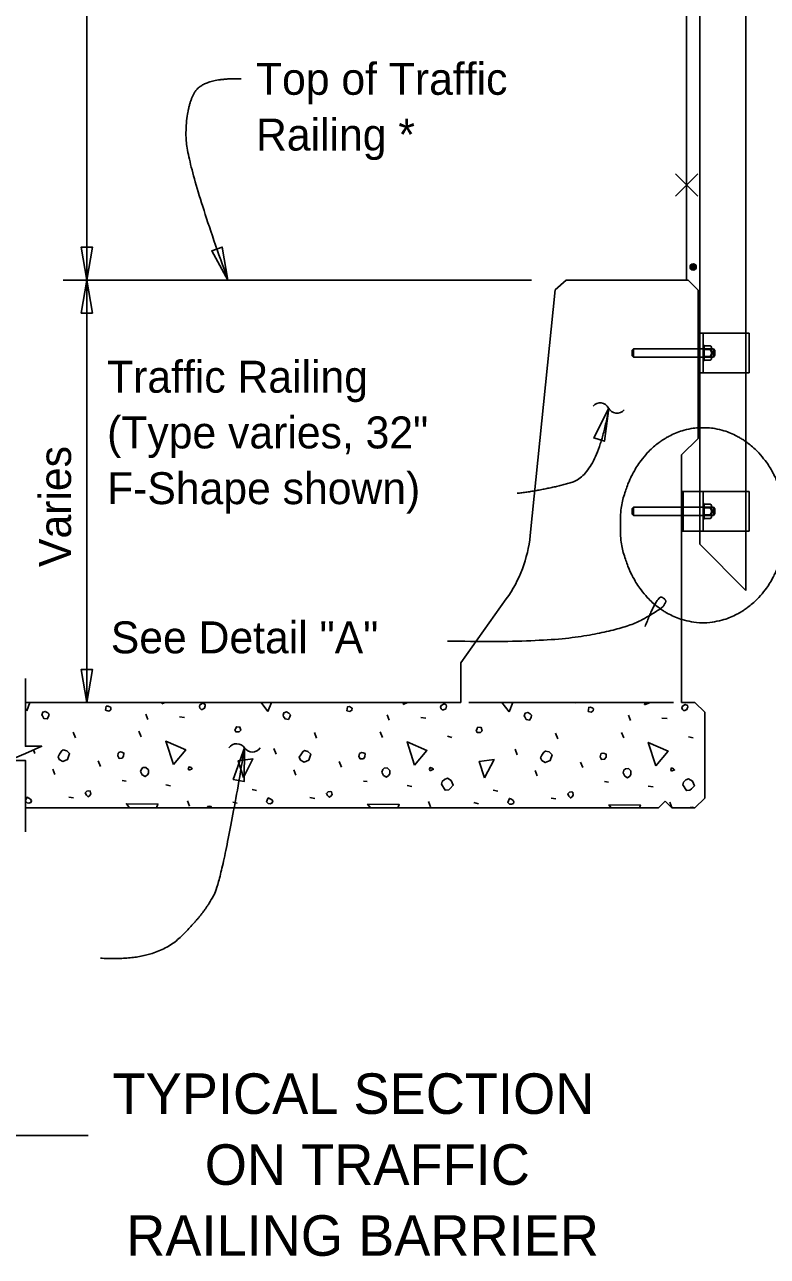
# Model space of a CAD drawing. Extents: x 0 to 41.1, y 0 to 25.9.
# Drawn here: x 29.01 to 33.7, y 11.06 to 18.84 of the extents above; entities that cross this region are included whole.
import ezdxf

# ---------------------------------------------------------------- set-up
doc = ezdxf.new("R2010")
doc.units = 0
for name, color, linetype in [('Dimension', 7, 'Continuous'), ('Miscellaneous', 7, 'Continuous'), ('SteelMisc', 7, 'Continuous'), ('SteelMisc_h', 7, 'Continuous'), ('SupstrConc', 7, 'Continuous'), ('SupstrConc_h', 7, 'Continuous'), ('TextStructures', 7, 'Continuous')]:
    doc.layers.add(name, color=color, linetype=linetype)

msp = doc.modelspace()

# ---------------------------------------------------------------- linework, layer by layer
at = {"layer": 'Dimension'}
for p, q in [((29.4061, 14.5579), (29.4061, 23.2246)), ((32.214, 17.2246), (29.2561, 17.2246)), ((23.6151, 11.8234), (29.4153, 11.8234))]:
    msp.add_line(p, q, dxfattribs=at)
for points in [[(29.4061, 17.2246), (29.3708, 17.4328), (29.4413, 17.4328)], [(30.2977, 17.2246), (30.2616, 17.4327), (30.1951, 17.4092)], [(29.4061, 17.2246), (29.3708, 17.0163), (29.4413, 17.0163)], [(32.7026, 16.4167), (32.6085, 16.2276), (32.676, 16.2071)], [(29.4061, 14.5579), (29.4413, 14.7662), (29.3708, 14.7662)], [(30.403, 14.2704), (30.3312, 14.0717), (30.4006, 14.0591)]]:
    msp.add_lwpolyline(points, close=True, dxfattribs=at)
msp.add_lwpolyline([(29.0176, 14.7079), (29.0176, 14.2808), (29.1209, 14.2808), (29.0176, 14.2358), (28.9142, 14.1908), (29.0176, 14.1908), (29.0176, 13.7412)], dxfattribs=at)
for centre, start, end in [((32.6489, 16.3894), 27.32823, 139.05545), ((32.7548, 16.4441), 207.32823, 319.05545), ((30.3527, 14.2371), 33.91896, 145.64618), ((30.4517, 14.3036), 213.91896, 325.64618)]:
    msp.add_arc(centre, 0.0596, start, end, dxfattribs=at)
for points, degree in [([(30.3802, 18.496), (30.1383, 18.5019), (30.0322, 18.3129), (30.0322, 17.9586), (30.2976, 17.2245)], 2), ([(32.1233, 15.878), (32.2959, 15.8977), (32.6322, 15.993), (32.7026, 16.4166)], 2), ([(33.2986, 15.0608), (33.3336, 15.0608), (33.3683, 15.0649), (33.4362, 15.0811), (33.4694, 15.0931), (33.5172, 15.1167), (33.5328, 15.1255), (33.5556, 15.14), (33.5631, 15.1451), (33.5779, 15.1557), (33.5851, 15.1612), (33.6208, 15.1896), (33.6471, 15.2155), (33.695, 15.2726), (33.7165, 15.3038), (33.7399, 15.3457), (33.7444, 15.3542), (33.7531, 15.3715), (33.7573, 15.3803), (33.7692, 15.4069), (33.7764, 15.4251), (33.8084, 15.5175), (33.8217, 15.5966), (33.8217, 15.7569), (33.8084, 15.836), (33.7764, 15.9283), (33.7692, 15.9465), (33.7573, 15.9731), (33.7531, 15.9819), (33.7444, 15.9992), (33.7399, 16.0077), (33.7165, 16.0496), (33.695, 16.0808), (33.6471, 16.138), (33.6208, 16.1638), (33.5851, 16.1923), (33.5779, 16.1978), (33.5631, 16.2083), (33.5556, 16.2134), (33.5328, 16.2279), (33.5172, 16.2367), (33.4694, 16.2603), (33.4362, 16.2724), (33.3683, 16.2885), (33.3336, 16.2926), (33.2636, 16.2926), (33.2289, 16.2885), (33.1609, 16.2724), (33.1278, 16.2603), (33.08, 16.2367), (33.0644, 16.2279), (33.0416, 16.2134), (33.0341, 16.2083), (33.0193, 16.1978), (33.0121, 16.1923), (32.9764, 16.1638), (32.9501, 16.138), (32.9022, 16.0808), (32.8807, 16.0496), (32.8573, 16.0077), (32.8527, 15.9992), (32.8441, 15.9819), (32.8399, 15.9731), (32.828, 15.9465), (32.8208, 15.9283), (32.7887, 15.836), (32.7755, 15.7569), (32.7755, 15.5966), (32.7887, 15.5175), (32.8208, 15.4251), (32.828, 15.4069), (32.8399, 15.3803), (32.8441, 15.3715), (32.8527, 15.3542), (32.8573, 15.3457), (32.8807, 15.3038), (32.9022, 15.2726), (32.9501, 15.2155), (32.9764, 15.1896), (33.0121, 15.1612), (33.0193, 15.1557), (33.0341, 15.1451), (33.0416, 15.14), (33.0644, 15.1255), (33.08, 15.1167), (33.1278, 15.0931), (33.1609, 15.0811), (33.2289, 15.0649), (33.2636, 15.0608), (33.2986, 15.0608)], 3), ([(31.6835, 14.9449), (32.2811, 14.9325), (32.8178, 15.0224), (33.0428, 15.1547), (33.0535, 15.1766), (33.0697, 15.2026), (33.0105, 15.2403), (32.9324, 15.0361)], 2), ([(29.4916, 12.9427), (29.8372, 12.9194), (30.1609, 13.2347), (30.2688, 13.477), (30.4029, 14.2707)], 2)]:
    msp.add_open_spline(points, degree=degree, dxfattribs=at)
at = {"layer": 'Miscellaneous'}
for p, q in [((33.2653, 17.8952), (33.1239, 17.7539)), ((33.1239, 17.8952), (33.2653, 17.7539)), ((33.2676, 16.8894), (33.278, 16.8894)), ((33.2712, 16.8894), (33.2712, 16.6394)), ((33.2745, 16.8894), (33.2745, 16.6394)), ((33.3586, 16.7756), (33.3586, 16.7548)), ((33.3683, 16.7756), (33.3683, 16.7548)), ((33.278, 16.6394), (33.2676, 16.6394)), ((33.1634, 15.8894), (33.1738, 15.8894)), ((33.167, 15.8894), (33.167, 15.6394)), ((33.1703, 15.8894), (33.1703, 15.6394)), ((33.3586, 15.7756), (33.3586, 15.7548)), ((33.3683, 15.7756), (33.3683, 15.7548)), ((33.1738, 15.6394), (33.1634, 15.6394)), ((30.9661, 14.5579), (30.9674, 14.5576)), ((32.4722, 14.5579), (32.4912, 14.5541)), ((29.7919, 14.4498), (29.7795, 14.4834)), ((31.3157, 14.4462), (31.3033, 14.4798)), ((32.8395, 14.4427), (32.8271, 14.4763)), ((29.9916, 14.4657), (30.0234, 14.4622)), ((31.5154, 14.4622), (31.5473, 14.4586)), ((33.0392, 14.4586), (33.0711, 14.4551)), ((29.334, 14.3349), (29.3199, 14.3702)), ((29.7494, 14.3402), (29.7353, 14.3755)), ((30.8578, 14.3313), (30.8437, 14.3667)), ((31.2732, 14.3366), (31.2591, 14.372)), ((31.6834, 14.3437), (31.7117, 14.3366)), ((32.3816, 14.3278), (32.3675, 14.3632)), ((32.7971, 14.3331), (32.7829, 14.3685)), ((33.2072, 14.3402), (33.2355, 14.3331)), ((29.0777, 14.2341), (29.0682, 14.2578)), ((30.6015, 14.2306), (30.5874, 14.2659)), ((32.1253, 14.227), (32.1112, 14.2624)), ((29.4913, 14.1528), (29.4772, 14.1882)), ((31.0152, 14.1493), (31.001, 14.1846)), ((32.539, 14.1457), (32.5248, 14.1811)), ((29.2032, 14.1015), (29.1908, 14.1351)), ((30.727, 14.098), (30.7146, 14.1316)), ((32.2508, 14.0945), (32.2384, 14.1281)), ((29.6292, 14.0644), (29.654, 14.0609)), ((29.905, 14.0361), (29.935, 14.0308)), ((30.4495, 14.0078), (30.4778, 14.0008)), ((31.153, 14.0609), (31.1778, 14.0573)), ((31.4288, 14.0326), (31.4589, 14.0273)), ((31.9733, 14.0043), (32.0016, 13.9972)), ((32.6769, 14.0573), (32.7016, 14.0538)), ((32.9526, 14.0291), (32.9827, 14.0238)), ((29.2916, 13.9601), (29.3216, 13.9548)), ((30.0535, 13.9018), (30.0411, 13.9354)), ((30.3275, 13.9283), (30.3558, 13.9212)), ((30.8154, 13.9566), (30.8454, 13.9513)), ((31.5773, 13.8982), (31.5649, 13.9318)), ((31.8513, 13.9248), (31.8796, 13.9177)), ((32.3392, 13.953), (32.3693, 13.9477)), ((33.1011, 13.8947), (33.0887, 13.9283))]:
    msp.add_line(p, q, dxfattribs=at)
for points in [[(33.1947, 23.2246), (33.1947, 17.2246)], [(29.0463, 14.5579), (29.0264, 14.5046)], [(29.8802, 14.5488), (29.8831, 14.5579)], [(29.9005, 14.5579), (29.8802, 14.5488)], [(30.1277, 14.5134), (30.1348, 14.5134), (30.1489, 14.5205), (30.1543, 14.5364), (30.1525, 14.5452), (30.1383, 14.5523), (30.1207, 14.5417), (30.1171, 14.5311), (30.1207, 14.5205), (30.1277, 14.5134)], [(30.5502, 14.501), (30.507, 14.5579)], [(30.5715, 14.5579), (30.5502, 14.501)], [(31.4041, 14.5452), (31.408, 14.5579)], [(31.4322, 14.5579), (31.4041, 14.5452)], [(31.6516, 14.5099), (31.6586, 14.5099), (31.6728, 14.517), (31.6781, 14.5329), (31.6763, 14.5417), (31.6622, 14.5488), (31.6445, 14.5382), (31.6409, 14.5276), (31.6445, 14.517), (31.6516, 14.5099)], [(32.074, 14.4975), (32.0282, 14.5579)], [(32.0966, 14.5579), (32.074, 14.4975)], [(32.9279, 14.5417), (32.9329, 14.5579)], [(32.9639, 14.5579), (32.9279, 14.5417)], [(29.0264, 14.5046), (29.0176, 14.5162)], [(29.1254, 14.4728), (29.1343, 14.4569), (29.1555, 14.4533), (29.1643, 14.4692), (29.1678, 14.4834), (29.159, 14.4922), (29.1431, 14.501), (29.1272, 14.4957), (29.1219, 14.4798), (29.1254, 14.4728)], [(29.5249, 14.5081), (29.5444, 14.5028), (29.5567, 14.5117), (29.5585, 14.524), (29.555, 14.5276), (29.5408, 14.5346), (29.5285, 14.5329), (29.5267, 14.5205), (29.5249, 14.5081)], [(30.6492, 14.4692), (30.6581, 14.4533), (30.6793, 14.4498), (30.6881, 14.4657), (30.6917, 14.4798), (30.6828, 14.4887), (30.6669, 14.4975), (30.651, 14.4922), (30.6457, 14.4763), (30.6492, 14.4692)], [(31.0487, 14.5046), (31.0682, 14.4993), (31.0806, 14.5081), (31.0823, 14.5205), (31.0788, 14.524), (31.0647, 14.5311), (31.0523, 14.5293), (31.0505, 14.517), (31.0487, 14.5046)], [(32.173, 14.4657), (32.1819, 14.4498), (32.2031, 14.4462), (32.2119, 14.4622), (32.2155, 14.4763), (32.2066, 14.4851), (32.1907, 14.494), (32.1748, 14.4887), (32.1695, 14.4728), (32.173, 14.4657)], [(32.5726, 14.501), (32.592, 14.4957), (32.6044, 14.5046), (32.6061, 14.517), (32.6026, 14.5205), (32.5885, 14.5276), (32.5761, 14.5258), (32.5743, 14.5134), (32.5726, 14.501)], [(33.1754, 14.5064), (33.1824, 14.5064), (33.1966, 14.5134), (33.2019, 14.5293), (33.2001, 14.5382), (33.186, 14.5452), (33.1683, 14.5346), (33.1648, 14.524), (33.1683, 14.5134), (33.1754, 14.5064)], [(30.3469, 14.372), (30.3682, 14.372), (30.3788, 14.3826), (30.3735, 14.4021), (30.3505, 14.4038), (30.3469, 14.3932), (30.3416, 14.3844), (30.3469, 14.372), (30.3434, 14.3755)], [(31.8708, 14.3685), (31.892, 14.3685), (31.9026, 14.3791), (31.8973, 14.3985), (31.8743, 14.4003), (31.8708, 14.3897), (31.8654, 14.3808), (31.8708, 14.3685), (31.8672, 14.372)], [(29.2315, 14.197), (29.2545, 14.1846), (29.2845, 14.197), (29.2969, 14.2341), (29.2792, 14.2518), (29.2562, 14.2571), (29.2456, 14.25), (29.2332, 14.2306), (29.2244, 14.2147), (29.2315, 14.197)], [(29.6009, 14.22), (29.6098, 14.2041), (29.6292, 14.2058), (29.6381, 14.2182), (29.6398, 14.2377), (29.6275, 14.243), (29.6186, 14.2447), (29.608, 14.2412), (29.6045, 14.2377), (29.6009, 14.22)], [(29.9527, 14.1652), (29.905, 14.3119), (30.0305, 14.2571), (29.9527, 14.1652)], [(30.7553, 14.1935), (30.7783, 14.1811), (30.8083, 14.1935), (30.8207, 14.2306), (30.803, 14.2483), (30.78, 14.2536), (30.7694, 14.2465), (30.7571, 14.227), (30.7482, 14.2111), (30.7553, 14.1935)], [(31.1248, 14.2164), (31.1336, 14.2005), (31.153, 14.2023), (31.1619, 14.2147), (31.1636, 14.2341), (31.1513, 14.2394), (31.1424, 14.2412), (31.1318, 14.2377), (31.1283, 14.2341), (31.1248, 14.2164)], [(31.4765, 14.1616), (31.4288, 14.3084), (31.5543, 14.2536), (31.4765, 14.1616)], [(32.2791, 14.1899), (32.3021, 14.1775), (32.3321, 14.1899), (32.3445, 14.227), (32.3268, 14.2447), (32.3039, 14.25), (32.2932, 14.243), (32.2809, 14.2235), (32.272, 14.2076), (32.2791, 14.1899)], [(32.6486, 14.2129), (32.6574, 14.197), (32.6769, 14.1988), (32.6857, 14.2111), (32.6875, 14.2306), (32.6751, 14.2359), (32.6662, 14.2377), (32.6556, 14.2341), (32.6521, 14.2306), (32.6486, 14.2129)], [(33.0004, 14.1581), (32.9526, 14.3048), (33.0781, 14.25), (33.0004, 14.1581)], [(30.3947, 14.0839), (30.3611, 14.1882), (30.4548, 14.2005), (30.3947, 14.0839)], [(31.9185, 14.0803), (31.8849, 14.1846), (31.9786, 14.197), (31.9185, 14.0803)], [(29.7459, 14.121), (29.7565, 14.0998), (29.7742, 14.0892), (29.7883, 14.0998), (29.7954, 14.1104), (29.7954, 14.1316), (29.7795, 14.1475), (29.76, 14.1457), (29.7512, 14.1369), (29.7459, 14.121)], [(30.0517, 14.1298), (30.0712, 14.1387), (30.0641, 14.1457), (30.0517, 14.151), (30.0464, 14.1387), (30.0517, 14.1298)], [(31.2697, 14.1174), (31.2803, 14.0962), (31.298, 14.0856), (31.3121, 14.0962), (31.3192, 14.1068), (31.3192, 14.1281), (31.3033, 14.144), (31.2839, 14.1422), (31.275, 14.1334), (31.2697, 14.1174)], [(31.5755, 14.1263), (31.595, 14.1351), (31.5879, 14.1422), (31.5755, 14.1475), (31.5702, 14.1351), (31.5755, 14.1263)], [(32.7935, 14.1139), (32.8041, 14.0927), (32.8218, 14.0821), (32.836, 14.0927), (32.843, 14.1033), (32.843, 14.1245), (32.8271, 14.1404), (32.8077, 14.1387), (32.7988, 14.1298), (32.7935, 14.1139)], [(33.0994, 14.1227), (33.1188, 14.1316), (33.1117, 14.1387), (33.0994, 14.144), (33.094, 14.1316), (33.0994, 14.1227)], [(31.6462, 14.0414), (31.6692, 14.0043), (31.6922, 14.0061), (31.701, 14.0149), (31.7205, 14.0344), (31.7081, 14.0644), (31.6834, 14.0786), (31.6657, 14.0715), (31.6516, 14.0573), (31.6462, 14.0414)], [(33.1701, 14.0379), (33.193, 14.0008), (33.216, 14.0025), (33.2249, 14.0114), (33.2443, 14.0308), (33.2319, 14.0609), (33.2072, 14.075), (33.1895, 14.0679), (33.1754, 14.0538), (33.1701, 14.0379)], [(29.0282, 13.923), (29.0406, 13.9212), (29.0529, 13.9265), (29.0565, 13.9371), (29.0512, 13.946), (29.0406, 13.953), (29.0282, 13.9583), (29.0211, 13.9442), (29.0176, 13.9336)], [(29.0176, 13.9336), (29.0282, 13.923)], [(29.403, 13.9725), (29.4136, 13.9619), (29.4242, 13.969), (29.4312, 13.9796), (29.4277, 13.9972), (29.4189, 13.999), (29.4065, 13.9972), (29.3959, 13.9866), (29.403, 13.9725)], [(30.552, 13.9195), (30.5644, 13.9177), (30.5767, 13.923), (30.5803, 13.9336), (30.575, 13.9424), (30.5644, 13.9495), (30.552, 13.9548), (30.5449, 13.9407), (30.5414, 13.9301), (30.552, 13.9195)], [(30.9268, 13.969), (30.9374, 13.9583), (30.948, 13.9654), (30.955, 13.976), (30.9515, 13.9937), (30.9427, 13.9955), (30.9303, 13.9937), (30.9197, 13.9831), (30.9268, 13.969)], [(32.0758, 13.9159), (32.0882, 13.9142), (32.1006, 13.9195), (32.1041, 13.9301), (32.0988, 13.9389), (32.0882, 13.946), (32.0758, 13.9513), (32.0687, 13.9371), (32.0652, 13.9265), (32.0758, 13.9159)], [(32.4506, 13.9654), (32.4612, 13.9548), (32.4718, 13.9619), (32.4789, 13.9725), (32.4753, 13.9902), (32.4665, 13.9919), (32.4541, 13.9902), (32.4435, 13.9796), (32.4506, 13.9654)], [(29.6759, 13.8912), (29.6557, 13.9177), (29.8555, 13.9159), (29.8462, 13.8912)], [(30.1932, 13.8912), (30.1913, 13.9003), (30.1825, 13.902), (30.1701, 13.9003), (30.161, 13.8912)], [(31.197, 13.8912), (31.1796, 13.9142), (31.3793, 13.9124), (31.3714, 13.8912)], [(32.7181, 13.8912), (32.7034, 13.9106), (32.9031, 13.9088), (32.8965, 13.8912)], [(33.2394, 13.8912), (33.239, 13.8932), (33.2301, 13.895), (33.2178, 13.8932), (33.2157, 13.8912)]]:
    msp.add_lwpolyline(points, dxfattribs=at)
at = {"layer": 'SteelMisc'}
for p, q in [((33.1947, 23.2245), (33.1947, 17.2245)), ((33.278, 16.8894), (33.278, 23.2245)), ((33.5697, 16.8894), (33.5697, 23.2245)), ((33.278, 16.6394), (33.278, 16.8894)), ((33.278, 16.8894), (33.5905, 16.8894)), ((33.2988, 16.8894), (33.2988, 16.6394)), ((33.5905, 16.8894), (33.5905, 16.6394)), ((33.3059, 16.8141), (33.2988, 16.8141)), ((33.3059, 16.8141), (33.3059, 16.7147)), ((33.3436, 16.8098), (33.3059, 16.8098)), ((33.3059, 16.719), (33.3059, 16.8098)), ((33.3438, 16.7871), (33.3059, 16.7871)), ((33.3438, 16.7418), (33.3059, 16.7418)), ((33.3523, 16.7303), (33.3523, 16.7985)), ((33.3635, 16.7902), (33.3523, 16.7902)), ((33.3635, 16.7387), (33.3523, 16.7387)), ((33.3635, 16.7902), (33.3635, 16.7387)), ((33.3732, 16.7805), (33.3635, 16.7902)), ((33.3732, 16.75), (33.3635, 16.7387)), ((33.3732, 16.7805), (33.3732, 16.75)), ((33.3059, 16.7147), (33.2988, 16.7147)), ((33.3436, 16.719), (33.3059, 16.719)), ((33.278, 15.5561), (33.278, 16.6394)), ((33.5905, 16.6394), (33.278, 16.6394)), ((33.5697, 15.8894), (33.5697, 16.6394)), ((33.1738, 15.6394), (33.1738, 15.8894)), ((33.1738, 15.8894), (33.278, 15.8894)), ((33.278, 15.8894), (33.5905, 15.8894)), ((33.2988, 15.8894), (33.2988, 15.6394)), ((33.5905, 15.8894), (33.5905, 15.6394)), ((33.3059, 15.8141), (33.2988, 15.8141)), ((33.3059, 15.8141), (33.3059, 15.7147)), ((33.3436, 15.8098), (33.3059, 15.8098)), ((33.3059, 15.719), (33.3059, 15.8098)), ((33.3523, 15.7303), (33.3523, 15.7985)), ((33.3059, 15.7147), (33.2988, 15.7147)), ((33.3438, 15.7871), (33.3059, 15.7871)), ((33.3438, 15.7418), (33.3059, 15.7418)), ((33.3436, 15.719), (33.3059, 15.719)), ((33.3635, 15.7902), (33.3523, 15.7902)), ((33.3635, 15.7387), (33.3523, 15.7387)), ((33.3635, 15.7902), (33.3635, 15.7387)), ((33.3732, 15.7805), (33.3635, 15.7902)), ((33.3732, 15.75), (33.3635, 15.7387)), ((33.3732, 15.7805), (33.3732, 15.75)), ((33.1738, 15.6394), (33.278, 15.6394)), ((33.5905, 15.6394), (33.278, 15.6394)), ((33.5697, 15.2644), (33.5697, 15.6394))]:
    msp.add_line(p, q, dxfattribs=at)
msp.add_lwpolyline([(33.278, 15.5561), (33.5697, 15.2644)], dxfattribs=at)
for radius in [0.0197, 0.0172, 0.0147, 0.0122, 0.00975, 0.00725, 0.00475, 0.00225]:
    msp.add_circle((33.2363, 17.3079), radius, dxfattribs=at)
for centre, radius, start, end in [((33.3405, 16.7984), 0.0118, 286.59863, 74.70054), ((33.3405, 16.7304), 0.0118, 285.15064, 73.50417), ((33.3176, 16.7644), 0.0347, 319.20147, 40.79853), ((33.3405, 15.7984), 0.0118, 286.59863, 74.70054), ((33.3405, 15.7304), 0.0118, 285.15064, 73.50417), ((33.3176, 15.7644), 0.0347, 319.20147, 40.79853)]:
    msp.add_arc(centre, radius, start, end, dxfattribs=at)
at = {"layer": 'SteelMisc_h'}
for p, q in [((33.5697, 16.8894), (33.5697, 16.6394)), ((32.859, 16.7904), (32.8509, 16.7822)), ((32.8509, 16.7822), (32.8509, 16.7465)), ((32.859, 16.7384), (32.8509, 16.7465)), ((33.3523, 16.7904), (32.859, 16.7904)), ((32.859, 16.7904), (32.859, 16.7384)), ((33.3523, 16.7384), (32.859, 16.7384)), ((33.5697, 15.8894), (33.5697, 15.6394)), ((32.859, 15.7904), (32.8509, 15.7822)), ((32.8509, 15.7822), (32.8509, 15.7465)), ((32.859, 15.7384), (32.8509, 15.7465)), ((33.3523, 15.7904), (32.859, 15.7904)), ((32.859, 15.7904), (32.859, 15.7384)), ((33.3523, 15.7384), (32.859, 15.7384))]:
    msp.add_line(p, q, dxfattribs=at)
at = {"layer": 'SupstrConc'}
for p, q in [((32.3654, 17.1623), (32.4342, 17.2245)), ((32.4343, 17.2246), (33.2051, 17.2246)), ((33.2051, 17.2245), (33.2676, 17.162)), ((32.2067, 15.611), (32.3654, 17.1623)), ((33.2676, 17.162), (33.2676, 16.2245)), ((33.2676, 16.2245), (33.1634, 16.1204)), ((33.1634, 16.1204), (33.1634, 14.5579)), ((31.7676, 14.8079), (32.0559, 15.2114)), ((31.7676, 14.5579), (31.7676, 14.8079)), ((29.0176, 14.5579), (31.7676, 14.5579)), ((33.1634, 14.5579), (33.2467, 14.5579)), ((33.2467, 14.5579), (33.3092, 14.4954)), ((33.3092, 14.4954), (33.3092, 13.9537)), ((33.0175, 13.8912), (33.0592, 13.9329)), ((33.0592, 13.9329), (33.1009, 13.8912)), ((33.3092, 13.9537), (33.2467, 13.8912)), ((33.0175, 13.8912), (29.0176, 13.8912)), ((33.2467, 13.8912), (33.1009, 13.8912))]:
    msp.add_line(p, q, dxfattribs=at)
msp.add_arc((31.3778, 15.6956), 0.8333, 324.46232, 354.16034, dxfattribs=at)
at = {"layer": 'SupstrConc_h'}
msp.add_line((33.1124, 14.5579), (31.8186, 14.5579), dxfattribs=at)

# ---------------------------------------------------------------- texts
at = {"layer": 'Dimension'}
for s, height, p in [('Top of Traffic ', 0.2016, (30.4747, 18.3949)), ('Railing *', 0.2016, (30.4747, 18.0429)), ('Traffic Railing ', 0.2016, (29.5341, 16.5137)), ('(Type varies, 32" ', 0.2016, (29.5341, 16.1617)), ('F-Shape shown)', 0.2016, (29.5341, 15.8097)), ('TYPICAL SECTION', 0.256001, (29.5683, 11.9589)), ('ON TRAFFIC', 0.256, (30.1511, 11.5109)), ('RAILING BARRIER', 0.256001, (29.6545, 11.0629))]:
    msp.add_text(s, height=height, dxfattribs=at).set_placement(p)
at = {"layer": 'TextStructures'}
msp.add_text('Varies', height=0.2016, rotation=90, dxfattribs=at).set_placement((29.3061, 15.4127))
msp.add_text('See Detail "A"', height=0.2016, dxfattribs=at).set_placement((29.5575, 14.8677))

doc.saveas('drawing.dxf')
